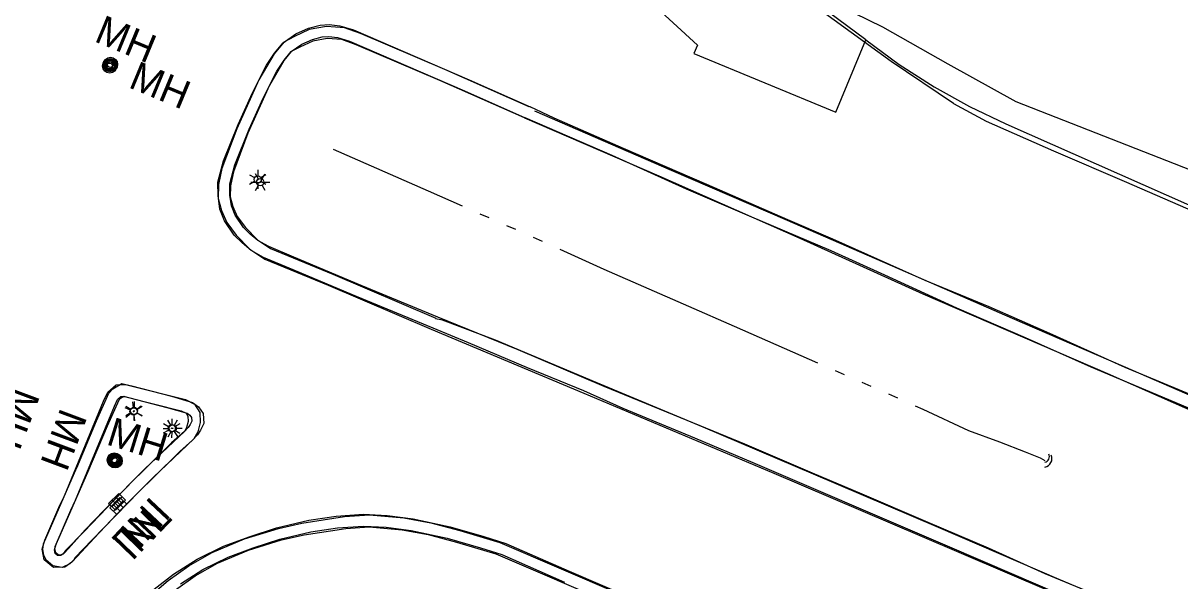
# Model space of a CAD drawing. Extents: x 588843 to 2552415, y 180129 to 269402.
# Drawn here: x 594189.5 to 594432.4, y 185313.2 to 185430.2 of the extents above; entities that cross this region are included whole.
import ezdxf

# ---------------------------------------------------------------- set-up
doc = ezdxf.new("R2010")
doc.units = 0
for name, color, linetype in [('Default', 7, 'Continuous'), ('E_DRN', 7, 'Continuous'), ('E_DRN_Text', 7, 'Continuous'), ('E_LTG', 7, 'Continuous'), ('E_RDWY', 7, 'Continuous'), ('E_RDWY_AsphConc', 7, 'Continuous'), ('E_RDWY_C_and_G', 7, 'Continuous'), ('E_RDWY_Gravel', 7, 'Continuous'), ('E_STRUCT_Joint', 7, 'Continuous'), ('E_UTL_MH', 7, 'Continuous'), ('E_UTL_MH_Text', 7, 'Continuous'), ('E_WTR_P', 7, 'Continuous')]:
    doc.layers.add(name, color=color, linetype=linetype)

# ---------------------------------------------------------------- blocks, each defined once
blk = doc.blocks.new('LPOL')
at = {"layer": 'Default'}
for p, q in [((-4, 0), (-1.5, 0)), ((-0.75, 1.3), (-2, 3.46)), ((0.75, 1.3), (2, 3.46)), ((1.5, 0), (4, 0)), ((-2, -3.46), (-0.75, -1.3)), ((2, -3.46), (0.75, -1.3))]:
    blk.add_line(p, q, dxfattribs=at)
for radius in [1.5, 1.5, 1.5, 0.125]:
    blk.add_circle((0, 0), radius, dxfattribs=at)
blk = doc.blocks.new('MHO')
at = {"layer": 'Default'}
for centre, radius in [((0.08, -0.12), 3), ((0.08, -0.12), 2.43), ((0.07, -0.15), 1.94), ((0.02, -0.16), 1.21)]:
    blk.add_circle(centre, radius, dxfattribs=at)
blk = doc.blocks.new('MHT')
at = {"layer": 'E_UTL_MH_Text'}
blk.add_text('MH', height=12, dxfattribs=at).set_placement((-9.81, -6))
blk = doc.blocks.new('INLO')
at = {"layer": 'E_DRN'}
for p, q in [((2, -4), (2, 0)), ((4, -4), (4, 0)), ((6, -2), (0, -2))]:
    blk.add_line(p, q, dxfattribs=at)
blk.add_lwpolyline([(0, -4), (6, -4), (6, 0), (0, 0), (0, -4)], close=True, dxfattribs=at)
blk = doc.blocks.new('INLT_21')
at = {"layer": 'E_DRN_Text'}
blk.add_text('INL', height=12, dxfattribs=at).set_placement((-11.03, -6))
blk = doc.blocks.new('CULV2')
at = {"layer": 'E_DRN'}
blk.add_arc((19.7, 14.8), 24.6, 216.8699, 323.1301, dxfattribs=at)
blk = doc.blocks.new('LPOL_4')
at = {"layer": 'E_LTG'}
for p, q in [((-13.1, 0), (-4.9, 0)), ((-2.5, 4.3), (-6.6, 11.4)), ((2.5, 4.3), (6.6, 11.4)), ((4.9, 0), (13.1, 0)), ((-6.6, -11.4), (-2.5, -4.3)), ((6.6, -11.4), (2.5, -4.3))]:
    blk.add_line(p, q, dxfattribs=at)
for radius in [4.92, 4.92, 4.92, 0.41]:
    blk.add_circle((0, 0), radius, dxfattribs=at)
blk = doc.blocks.new('CULV2_4')
at = {"layer": 'E_DRN'}
blk.add_arc((65, 48), 80.7, 216.8699, 323.1301, dxfattribs=at)
blk = doc.blocks.new('MHO_3')
at = {"layer": 'E_UTL_MH'}
for centre, radius in [((0.3, -0.4), 9.84), ((0.3, -0.4), 7.98), ((0.2, -0.5), 6.35), ((0.1, -0.5), 3.97)]:
    blk.add_circle(centre, radius, dxfattribs=at)
blk = doc.blocks.new('MHT_3')
at = {"layer": 'E_UTL_MH_Text'}
blk.add_text('MH', height=39.37, dxfattribs=at).set_placement((-32.2, -19.7))
blk = doc.blocks.new('INLO_3')
at = {"layer": 'E_DRN'}
for p, q in [((6.6, -13.1), (6.6, 0)), ((13.1, -13.1), (13.1, 0)), ((19.7, -6.6), (0, -6.6))]:
    blk.add_line(p, q, dxfattribs=at)
blk.add_lwpolyline([(0, -13.1), (19.7, -13.1), (19.7, 0), (0, 0)], close=True, dxfattribs=at)
blk = doc.blocks.new('INLT_37_1')
at = {"layer": 'E_DRN_Text'}
blk.add_text('INL', height=39.37, dxfattribs=at).set_placement((-36.2, -19.7))

msp = doc.modelspace()

# ---------------------------------------------------------------- linework, layer by layer
at = {"layer": 'E_RDWY'}
for points in [[(594384.9, 185413.36), (594371.77, 185422.17), (594351.44, 185437), (594329.34, 185453.15), (594324.09, 185457.72), (594322.86, 185458.79), (594319.65, 185461.8)], [(594420.98, 185358), (594405.14, 185365.11), (594392.38, 185370.72), (594378.96, 185376.24), (594359.57, 185384.92), (594350.1, 185388.96), (594333.07, 185396.36), (594315.56, 185403.93), (594300.99, 185410.31), (594295.97, 185412.67)], [(594296.88, 185411.87), (594325.62, 185399.4), (594349.95, 185388.9), (594374.77, 185378.12), (594397.2, 185368.32), (594422.63, 185357.35), (594444.66, 185347.72), (594469.29, 185337.04), (594493.12, 185326.74), (594515.85, 185316.9), (594539.82, 185306.36), (594564.27, 185295.73), (594590.16, 185284.43), (594616.48, 185273), (594638.84, 185263.28), (594667.59, 185250.7), (594695.94, 185238.13), (594716.7, 185228.91), (594730.42, 185222.27), (594740.31, 185216.94), (594750.4, 185211.08), (594752.94, 185209.36)], [(594384.9, 185413.36), (594391.73, 185409.66), (594405.93, 185403.45), (594421.24, 185396.86), (594441.64, 185388), (594473.72, 185373.96), (594499.14, 185363.15), (594519.99, 185354.07), (594541.44, 185344.6), (594561.26, 185335.85), (594580.09, 185327.6), (594600.85, 185318.74), (594621.43, 185309.42), (594642.83, 185300.12), (594664.5, 185290.7), (594686.69, 185280.92), (594710.89, 185270.31), (594732.2, 185260.72), (594752.9, 185251.83), (594767.48, 185245.51)], [(594275.19, 185366), (594307.23, 185352.56), (594347.18, 185335.8), (594377.84, 185322.73), (594414.5, 185307.01), (594452.18, 185290.9)], [(594307.24, 185353.09), (594295.4, 185357.91), (594283.04, 185363.11), (594275.63, 185366.23)], [(594436.63, 185351.46), (594420.98, 185358)], [(594432.33, 185299.59), (594414.88, 185307.06), (594397.67, 185314.47), (594383.63, 185320.44), (594368.93, 185326.78), (594354.56, 185332.89), (594342.82, 185337.93), (594330.54, 185343.14), (594315.54, 185349.36), (594307.24, 185353.09)]]:
    msp.add_lwpolyline(points, dxfattribs=at)
at = {"layer": 'E_RDWY_AsphConc'}
for points in [[(594366.49, 185426.77), (594348.92, 185439.79), (594341.71, 185444.75), (594329.72, 185453.84), (594322.75, 185462.35)], [(594360.2, 185411.55), (594366.49, 185426.77), (594373.5, 185421.59), (594380.82, 185416.88), (594380.82, 185416.88), (594388.23, 185412.75), (594395.88, 185409.09), (594395.88, 185409.09), (594443.66, 185388.01), (594493.88, 185365.82), (594538.94, 185345.93)]]:
    msp.add_lwpolyline(points, dxfattribs=at)
at = {"layer": 'E_RDWY_C_and_G'}
for points in [[(594266.84, 185488.52), (594272.51, 185482.26), (594283.99, 185470.57), (594295.62, 185459.03), (594295.62, 185459.03), (594313.21, 185442.15), (594331.12, 185425.62), (594331.12, 185425.62), (594330.36, 185423.88)], [(594275.63, 185366.23), (594259.53, 185372.85), (594245.35, 185378.81), (594239.97, 185381.08), (594237.37, 185382.55), (594235.48, 185384.1), (594233.84, 185385.77), (594231.79, 185388.77), (594230.8, 185391.23), (594230.43, 185393.98), (594230.4, 185396.85), (594231.57, 185401.31), (594234.63, 185408.95), (594237.63, 185415.6), (594240.6, 185421.43), (594242.29, 185423.96), (594244.07, 185426.11), (594246.79, 185428.03), (594249.4, 185429.17), (594251.88, 185429.85), (594253.76, 185429.95), (594256.02, 185429.69), (594258.91, 185428.85), (594283.16, 185418.33), (594295.97, 185412.67)], [(594295.78, 185412.67), (594278.04, 185420.51), (594260.34, 185428.05), (594256.99, 185429.24), (594253.24, 185429.57), (594249.56, 185428.88), (594246.51, 185427.46), (594244.21, 185426.28), (594242.18, 185423.82), (594239, 185418.35), (594234.39, 185408.09), (594231.25, 185399.7), (594230.54, 185396.4), (594230.47, 185393.46), (594231.17, 185390.92), (594232.29, 185388.4), (594234.24, 185385.71), (594237.1, 185382.81), (594240.28, 185380.72), (594253.59, 185375.25), (594275.19, 185366)], [(594276.58, 185368.54), (594260.49, 185375.15), (594246.32, 185381.12), (594241.07, 185383.33), (594238.79, 185384.62), (594237.17, 185385.94), (594235.78, 185387.36), (594234.01, 185389.96), (594233.24, 185391.88), (594232.93, 185394.16), (594232.9, 185396.55), (594233.95, 185400.53), (594236.93, 185407.97), (594239.88, 185414.52), (594242.76, 185420.17), (594244.3, 185422.47), (594245.78, 185424.26), (594248.02, 185425.84), (594250.24, 185426.8), (594252.28, 185427.37), (594253.68, 185427.44), (594255.52, 185427.23), (594258.07, 185426.49), (594282.16, 185416.04), (594294.96, 185410.38)], [(594294.77, 185410.38), (594277.04, 185418.22), (594259.43, 185425.72), (594256.46, 185426.78), (594253.36, 185427.05), (594250.33, 185426.48), (594247.61, 185425.21), (594245.81, 185424.29), (594244.24, 185422.39), (594241.23, 185417.21), (594236.71, 185407.14), (594233.66, 185399), (594233.04, 185396.11), (594232.98, 185393.77), (594233.53, 185391.76), (594234.47, 185389.65), (594236.16, 185387.33), (594238.7, 185384.76), (594241.45, 185382.94), (594254.55, 185377.56), (594276.17, 185368.3)], [(594200.78, 185336.94), (594204.91, 185346.74), (594207.52, 185352.58), (594208.33, 185353.46), (594210.19, 185354.6), (594212.23, 185354.12), (594220.62, 185351.93), (594225.07, 185350.65), (594226.3, 185349.73), (594227.3, 185348.32), (594227.43, 185346.21), (594226.72, 185344.78), (594226.14, 185343.86), (594225.09, 185342.75), (594222.39, 185340.36), (594217.01, 185335.05), (594213.76, 185331.87)], [(594203.08, 185335.97), (594207.21, 185345.74), (594209.64, 185351.19), (594209.93, 185351.51), (594210.62, 185351.93), (594211.62, 185351.7), (594219.96, 185349.51), (594223.93, 185348.38), (594224.48, 185347.96), (594224.85, 185347.45), (594224.89, 185346.72), (594224.54, 185346), (594224.16, 185345.4), (594223.35, 185344.55), (594220.68, 185342.19), (594215.26, 185336.83), (594212.01, 185333.66)], [(594213.86, 185331.97), (594204.02, 185321.77), (594200.38, 185318.05), (594200.11, 185317.61), (594199.31, 185316.74), (594197.67, 185315.96), (594195.74, 185316.31), (594194.32, 185317.52), (594193.86, 185318.61), (594193.65, 185319.74), (594193.75, 185320.99), (594200.79, 185336.97)], [(594212.06, 185333.7), (594202.23, 185323.51), (594198.39, 185319.59), (594198.1, 185319.11), (594197.8, 185318.79), (594197.33, 185318.57), (594196.84, 185318.65), (594196.39, 185319.04), (594196.27, 185319.33), (594196.17, 185319.87), (594196.21, 185320.37), (594203.08, 185335.97)], [(594205.39, 185298.7), (594207.73, 185301.54), (594211.63, 185305.72), (594215.21, 185309.17), (594219.93, 185313.26), (594224.29, 185316.34), (594229.19, 185319.15), (594235.96, 185321.98), (594243.1, 185324.2), (594248.05, 185325.28), (594257, 185326.7), (594262.21, 185327.03), (594269.45, 185326.4), (594275.12, 185325.37), (594281.22, 185323.74), (594289.63, 185321.22), (594314.89, 185310.42)], [(594217.04, 185311.42), (594221.07, 185314.57), (594226.01, 185317.76), (594231.58, 185320.45), (594236.96, 185322.45), (594242.7, 185324.35), (594249.47, 185325.93), (594255.22, 185326.79), (594260.97, 185327.19), (594265.96, 185326.92), (594271.43, 185326.24), (594279.18, 185324.55), (594286.24, 185322.5), (594290.89, 185321.04), (594304.17, 185315.22), (594318.14, 185309.23)], [(594207.32, 185297.11), (594209.61, 185299.89), (594213.41, 185303.97), (594216.9, 185307.33), (594221.47, 185311.29), (594225.64, 185314.23), (594230.3, 185316.91), (594236.82, 185319.63), (594243.74, 185321.78), (594248.51, 185322.82), (594257.28, 185324.21), (594262.19, 185324.53), (594269.12, 185323.92), (594274.57, 185322.93), (594280.54, 185321.34), (594288.78, 185318.87), (594313.91, 185308.12)], [(594222.52, 185312.53), (594227.24, 185315.58), (594232.56, 185318.15), (594237.79, 185320.09), (594243.38, 185321.94), (594249.94, 185323.47), (594255.5, 185324.3), (594260.99, 185324.69), (594265.74, 185324.43), (594271, 185323.77), (594278.57, 185322.13), (594285.52, 185320.1), (594290.01, 185318.7), (594303.18, 185312.92)]]:
    msp.add_lwpolyline(points, dxfattribs=at)
for points in [[(594198.16, 185331.06), (594202.6, 185341.73), (594206.39, 185350.88), (594207.3, 185352.8), (594209.04, 185354.3), (594211, 185354.41), (594223.57, 185351.25), (594225.45, 185350.27), (594226.58, 185348.55), (594226.65, 185346.41), (594226.18, 185344.44), (594225.33, 185342.98), (594216.84, 185334.96), (594210.29, 185328.34), (594204.38, 185322.17), (594200.87, 185318.28), (594199.75, 185317.13), (594198.23, 185316.04), (594195.84, 185315.98), (594193.91, 185317.58), (594193.48, 185319.83), (594194.06, 185321.76), (594197.22, 185329.04), (594198.16, 185331.06)], [(594200.47, 185330.1), (594204.91, 185340.77), (594208.68, 185349.87), (594209.33, 185351.25), (594210.02, 185351.85), (594210.76, 185351.89), (594222.68, 185348.89), (594223.72, 185348.35), (594224.11, 185347.77), (594224.14, 185346.66), (594223.83, 185345.38), (594223.35, 185344.55), (594215.09, 185336.75), (594208.5, 185330.08), (594202.55, 185323.87), (594199.05, 185319.99), (594198.11, 185319.03), (594197.4, 185318.52), (594196.71, 185318.5), (594196.2, 185318.93), (594196.05, 185319.69), (594196.41, 185320.9), (594199.51, 185328.04), (594200.47, 185330.1)]]:
    msp.add_lwpolyline(points, close=True, dxfattribs=at)
at = {"layer": 'E_RDWY_Gravel'}
for points in [[(594348.92, 185439.79), (594369.96, 185429.46), (594383.73, 185421.69), (594397.97, 185413.82), (594446.4, 185394.86), (594449.62, 185401.06), (594450.88, 185405.43), (594456.18, 185415.68), (594467.5, 185410.59), (594464.66, 185399.74), (594464.07, 185391.84), (594466.01, 185388.04), (594494.93, 185369.91), (594541.17, 185349.71)], [(594294.77, 185410.38), (594323, 185398.2), (594352.64, 185385.11), (594378.47, 185373.42), (594417.21, 185356.7), (594461.03, 185337.4), (594502.73, 185319.22), (594545.58, 185300.1), (594582.07, 185284.13), (594624.08, 185265.97), (594659.78, 185250.12), (594703.03, 185231.29), (594732.78, 185218.27), (594752.76, 185209.38), (594752.81, 185209.45)], [(594413.84, 185358.07), (594400, 185364.2), (594385.58, 185370.45), (594370.49, 185377.35), (594359.17, 185382.44), (594342.03, 185389.74), (594328.82, 185395.43), (594313.23, 185402.46), (594294.96, 185410.38)], [(594542.22, 185255.2), (594523.14, 185263.83), (594514.37, 185267.87), (594497.56, 185274.99), (594478.07, 185283.43), (594456.69, 185292.47), (594432.43, 185302.84), (594407.11, 185313.47), (594381.72, 185324.42), (594355.48, 185335.56), (594332.34, 185345.41), (594309.84, 185354.82), (594288.72, 185363.68), (594277.6, 185367.93), (594276.13, 185368.21)], [(594311.49, 185354.01), (594293.45, 185361.68), (594276.58, 185368.54)], [(594436.77, 185348.38), (594413.84, 185358.07)], [(594432.55, 185302.93), (594417.06, 185309.31), (594404.17, 185314.66), (594392.23, 185320.07), (594379.09, 185325.68), (594365.73, 185331.41), (594355.3, 185335.77), (594341.06, 185341.9), (594328.98, 185346.87), (594311.49, 185354.01)]]:
    msp.add_lwpolyline(points, dxfattribs=at)
at = {"layer": 'E_STRUCT_Joint'}
msp.add_lwpolyline([(594330.36, 185423.88), (594360.2, 185411.55)], dxfattribs=at)
at = {"layer": 'E_WTR_P'}
for points in [[(594254.63, 185403.81), (594274.55, 185395.04), (594281.7, 185391.89)], [(594285.43, 185390.25), (594287.3, 185389.43)], [(594291.03, 185387.79), (594292.9, 185386.97)], [(594296.63, 185385.32), (594298.49, 185384.48)], [(594302.2, 185382.81), (594311.43, 185378.64), (594329.23, 185370.82)], [(594329.23, 185370.82), (594338.8, 185366.61), (594356.33, 185358.97)], [(594360.06, 185357.34), (594361.93, 185356.52)], [(594365.66, 185354.88), (594367.53, 185354.05)], [(594371.26, 185352.41), (594373.12, 185351.58)], [(594376.85, 185349.93), (594378.47, 185349.22), (594388.04, 185344.74), (594394.53, 185342.37), (594399.98, 185340.3), (594403.09, 185339), (594404.05, 185338.42)]]:
    msp.add_lwpolyline(points, dxfattribs=at)

# ---------------------------------------------------------------- block references
at = {"layer": 'E_DRN'}
for name, p, xscale, yscale, rotation in [('CULV2_4', (594404.07, 185337.08), 0.021828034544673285, 0.021828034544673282, 61.935464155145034), ('CULV2', (594404.1, 185338.11), 0.04760984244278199, 0.047609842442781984, 64.20005845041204), ('INLO', (594210.99, 185330.1), 0.5, 0.5, -135.38814367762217), ('INLO_3', (594211.25, 185329.27), 0.15240030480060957, 0.15240030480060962, -133.9605535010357)]:
    msp.add_blockref(name, p, dxfattribs=dict(at, xscale=xscale, yscale=yscale, rotation=rotation))
at = {"layer": 'E_DRN_Text'}
for name, p, xscale, yscale, rotation in [('INLT_21', (594214.83, 185325.06), 0.49999999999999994, 0.49999999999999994, -133.2354227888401), ('INLT_37_1', (594214.04, 185323.24), 0.15240030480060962, 0.15240030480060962, 46.039446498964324)]:
    msp.add_blockref(name, p, dxfattribs=dict(at, xscale=xscale, yscale=yscale, rotation=rotation))
at = {"layer": 'E_LTG'}
for name, p, xscale, yscale, rotation in [('LPOL', (594238.76, 185397.45), 0.5000000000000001, 0.5, -89.67337617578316), ('LPOL_4', (594239.29, 185396.87), 0.15240030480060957, 0.15240030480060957, 0.8014450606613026), ('LPOL_4', (594212.68, 185348.74), 0.1524003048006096, 0.15240030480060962, -84.36014555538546), ('LPOL', (594212.77, 185348.86), 0.5000000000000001, 0.5, -90.72490345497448), ('LPOL_4', (594220.92, 185345.2), 0.15240030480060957, 0.15240030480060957, 0.8014450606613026), ('LPOL', (594220.7, 185345.21), 0.5000000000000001, 0.5, -90.72490345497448)]:
    msp.add_blockref(name, p, dxfattribs=dict(at, xscale=xscale, yscale=yscale, rotation=rotation))
at = {"layer": 'E_UTL_MH'}
for name, p, xscale, yscale, rotation in [('MHO_3', (594207.66, 185421.33), 0.1524003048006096, 0.1524003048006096, -22.471395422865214), ('MHO', (594207.82, 185421.65), 0.4999999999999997, 0.4999999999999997, -22.447224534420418), ('MHO_3', (594208.78, 185338.46), 0.15240030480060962, 0.1524003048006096, -17.222711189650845), ('MHO', (594208.7, 185338.6), 0.5000000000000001, 0.5, -90.72490345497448)]:
    msp.add_blockref(name, p, dxfattribs=dict(at, xscale=xscale, yscale=yscale, rotation=rotation))
at = {"layer": 'E_UTL_MH_Text'}
for name, p, xscale, yscale, rotation in [('MHT', (594209.88, 185427.4), 0.4999999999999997, 0.4999999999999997, -22.447224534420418), ('MHT_3', (594217.07, 185417.73), 0.1524003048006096, 0.1524003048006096, -22.471395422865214), ('MHT', (594188.57, 185348.48), 0.49999999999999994, 0.49999999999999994, -110.51581262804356), ('MHT', (594198.49, 185344.04), 0.49999999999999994, 0.49999999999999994, -110.51581262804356), ('MHT_3', (594212.31, 185343.29), 0.15240030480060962, 0.1524003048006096, -17.222711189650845)]:
    msp.add_blockref(name, p, dxfattribs=dict(at, xscale=xscale, yscale=yscale, rotation=rotation))

doc.saveas('drawing.dxf')
